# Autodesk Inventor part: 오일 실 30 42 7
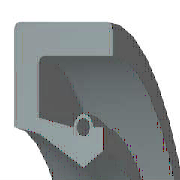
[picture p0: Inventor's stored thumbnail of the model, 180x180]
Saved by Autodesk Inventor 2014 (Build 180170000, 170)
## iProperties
IsCustomPart: 1
Created: 2012-02
Part Number: 오일 실 30 42 7
Material: 고무
Description: 오일 실 - 스프링 장착, 금속 케이스 SM
Document SubType Name: Modeling
Standard: JIS B 2402
Designer: mdu-01
Standards Organization: JIS
Language: ko-KR
Size Designation: 30 42 7 A
Categories: <MemberInstance><Categories><Category DisplayName="샤프트 부품" InternalName="7f7aeb1f-a693-4053-b835-cee3144e0d98" Mnemonic="SHFT"><Category DisplayName="실링" Intern
Density: 0.93 g/cm^3
Appearance: Rubber-Black
Mass: 2.53106 g
Surface Area: 36.9849 cm^2
Volume: 2.72157 cm^3
Author: mdu-01
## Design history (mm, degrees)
body "Solid1"
revolve "회전1" stored, may be unused: angle "d33" = 360 deg
fillet "모깎기1" dims "d34" = 0.35 (= 0.05 x b)
chamfer "모따기1" distance "d35" = 0.7 (= 0.1 x b); stored, may be unused: second distance "d36" = 0.35 (= 0.05 x b), angle "d41" = 45 deg
sketch "스케치2"
  geometry: L1 (16.457, -5.158)-(17.021, -7); L2 (15.857, -4.55)-(16.457, -5.158); L3 (15, -1.75)-(15.857, -4.55); L4 (15.8, -0.875)-(15, -1.75); L5 (17.141, -0.875)-(15.8, -0.875); L6 (17.141, -1.575)-(17.141, -0.875); L7 (17.141, -5.25)-(17.141, -2.975); L8 (18.6, -5.25)-(17.141, -5.25); L9 (19.8, -1.75)-(18.6, -5.25); L10 (19.8, 0)-(19.8, -1.75); L11 (21, 0)-(19.8, 0); L12 (21, -7)-(21, 0); L13 (17.021, -7)-(21, -7); L14 (0, -9.6)-(0, 1.6) reference; L15 (28, 0)-(14, 0) reference; A1 r 0.7 centre (17.141, -2.275) between (17.141, -2.975) and (17.141, -1.575)
  constraints: 26 end point, 4 horizontal, 4 vertical, 2 point on circle, 1 centre point, 1 collinear, 1 parallel
  dimensions: "d2" = 7 distance of L12.start L11.start (= b); "d4" = 0.875 vertical distance of L10.start L5.start (= 0.125 x b); "d6" = 1.2 distance of L11.start L10.start (= 0.1 x dd - 0.1 x Diam); "d8" = 1.75 distance of L10.start L9.start (= 0.25 x b); "d10" = 1.75 vertical distance of L8.start L1.end (= 0.25 x b); "d12" = 1.2 horizontal distance of L9.start L8.start (= 0.1 x dd - 0.1 x Diam); "d14" = 0.7 radius of A1 (= 0.1 x b); "d16" = 0 horizontal distance of A1.centre L7.end; "d18" = 0.7 distance of L6.start L5.start (= 0.1 x b); "d20" = 0.8 horizontal distance of L4.start L3.start (= 0.0666667 x dd - 0.0666667 x Diam); "d22" = 0.12 horizontal distance of L7.start L1.end (= 0.01 x dd - 0.01 x Diam); "d24" = 0.875 vertical distance of L4.start L3.start (= 0.125 x b); "d26" = 2.8 vertical distance of L3.start L2.start (= 0.4 x b); "d28" = 0.85714 horizontal distance of L3.start L2.start (= 0.0714286 x dd - 0.0714286 x Diam); "d30" = 1.84211 vertical distance of L1.start L1.end (= 0.263158 x b); "d32" = 0.6 horizontal distance of L2.start L1.start (= 0.05 x dd - 0.05 x Diam); "d37" = 0 distance between parallel lines of L15 L11; "d38" = 21 distance between parallel lines of L14 L12 (= 0.5 x dd); "d39" = 15 distance from line of L14 L3.start (= 0.5 x Diam)
other parameters: "dd" = 42 [user parameter; used in 7 equation terms], "b" = 7 [user parameter; used in 12 equation terms], "d1" = 8 (derived), "d3" = 1 (derived), "d5" = 2 (derived), "d7" = 2 (derived), "d9" = 2 (derived), "d11" = 2 (derived), "d13" = 0.8 (derived), "d15" = 0 (derived), "d17" = 0.8 (derived), "d19" = 1.33333 (derived), "d21" = 0.2 (derived), "d23" = 1 (derived), "d25" = 3.2 (derived), "d27" = 1.42857 (derived), "d29" = 2.10526 (derived), "d31" = 1 (derived), "d40" = 0
